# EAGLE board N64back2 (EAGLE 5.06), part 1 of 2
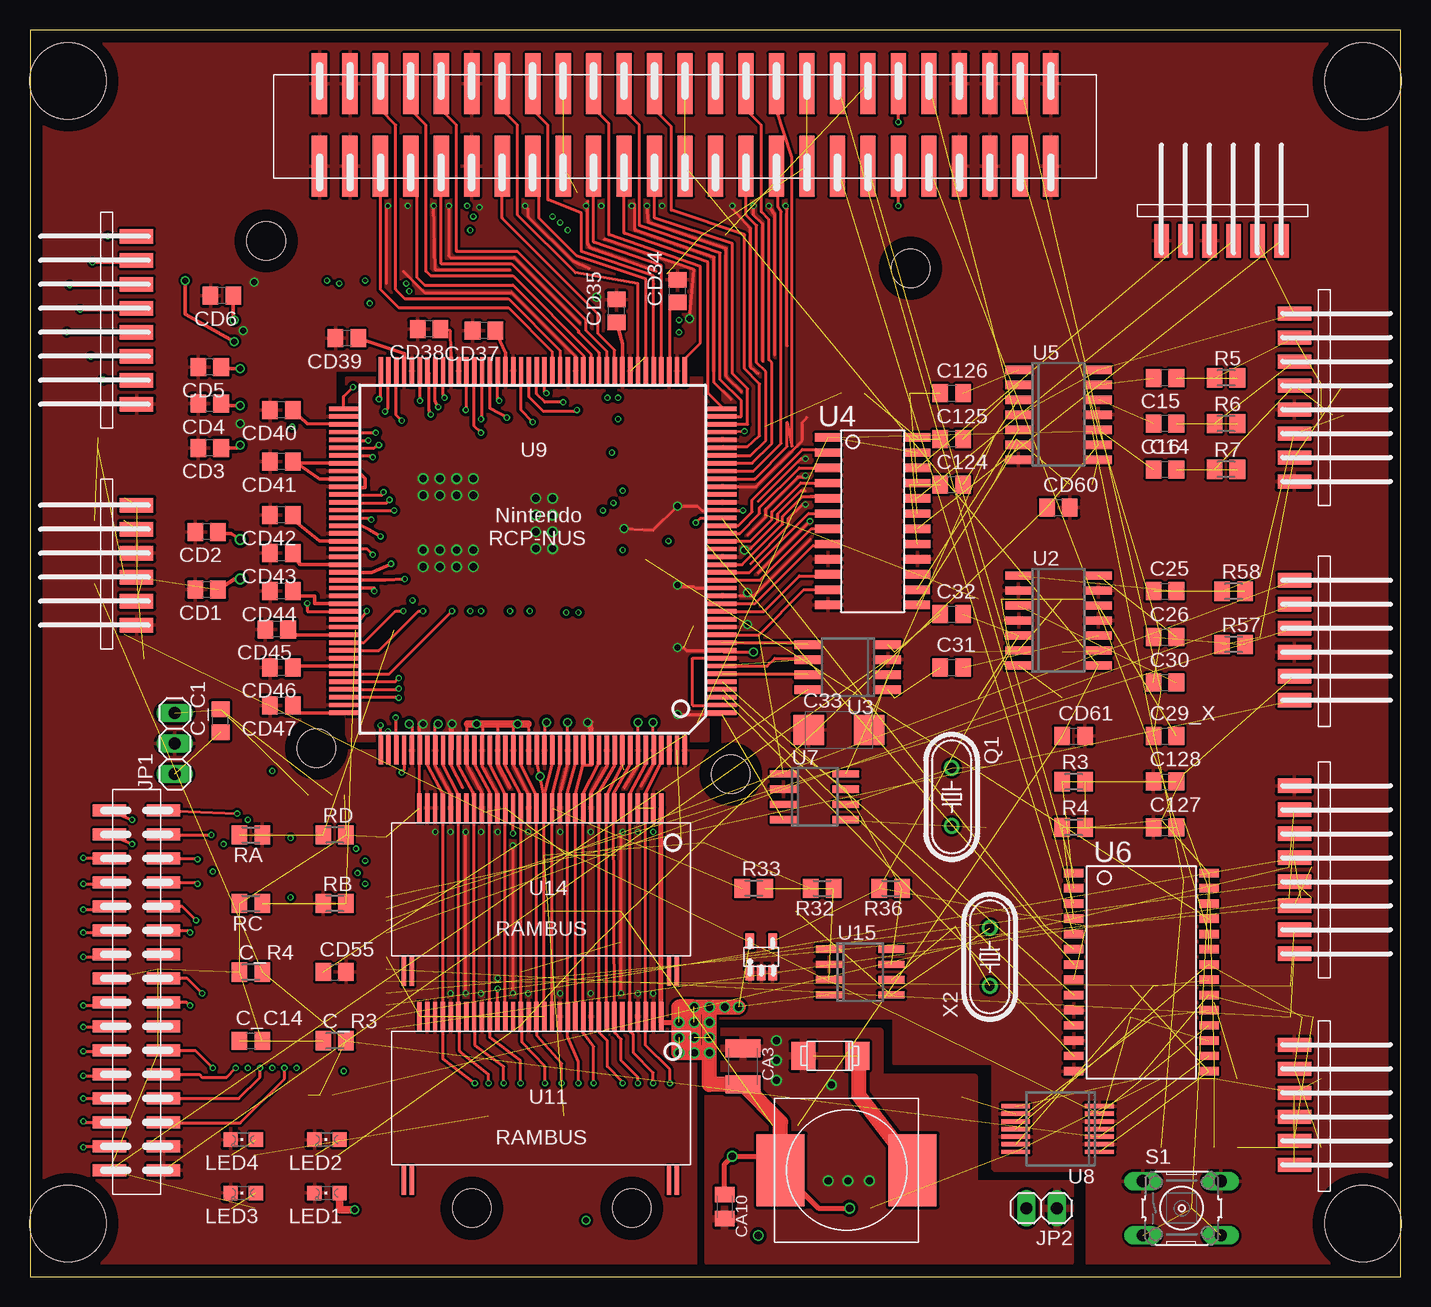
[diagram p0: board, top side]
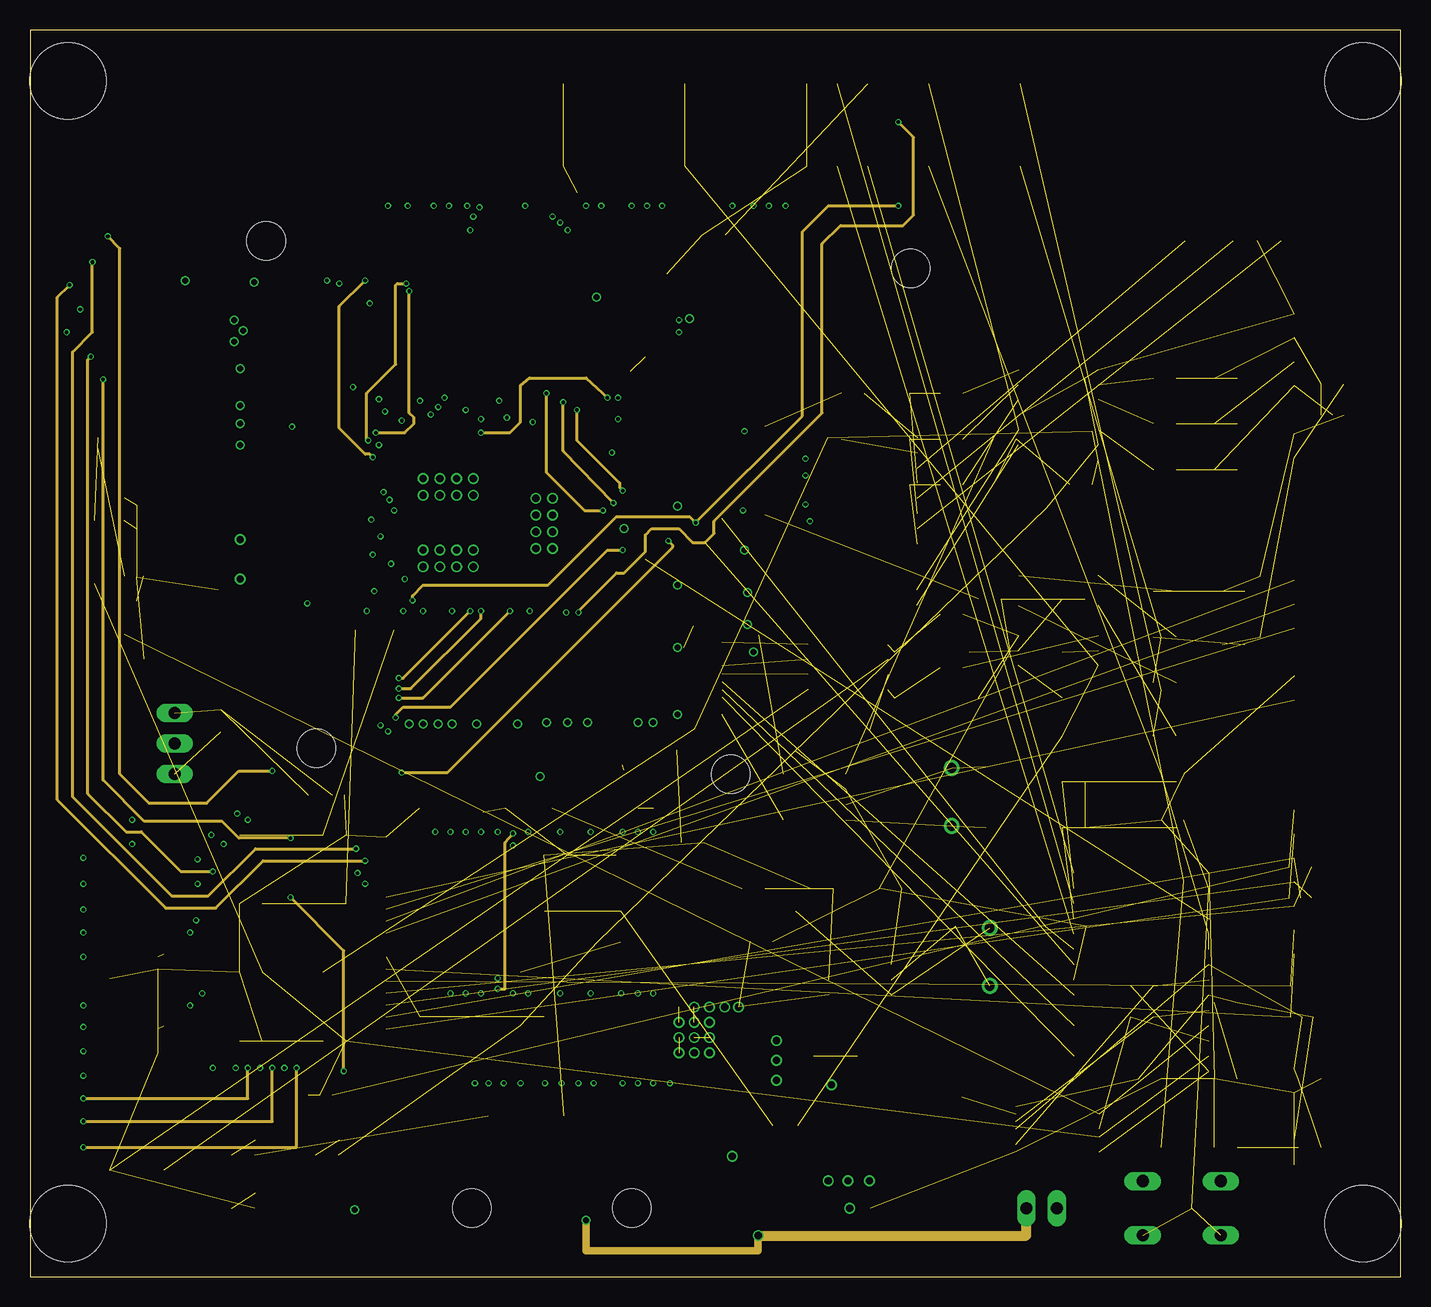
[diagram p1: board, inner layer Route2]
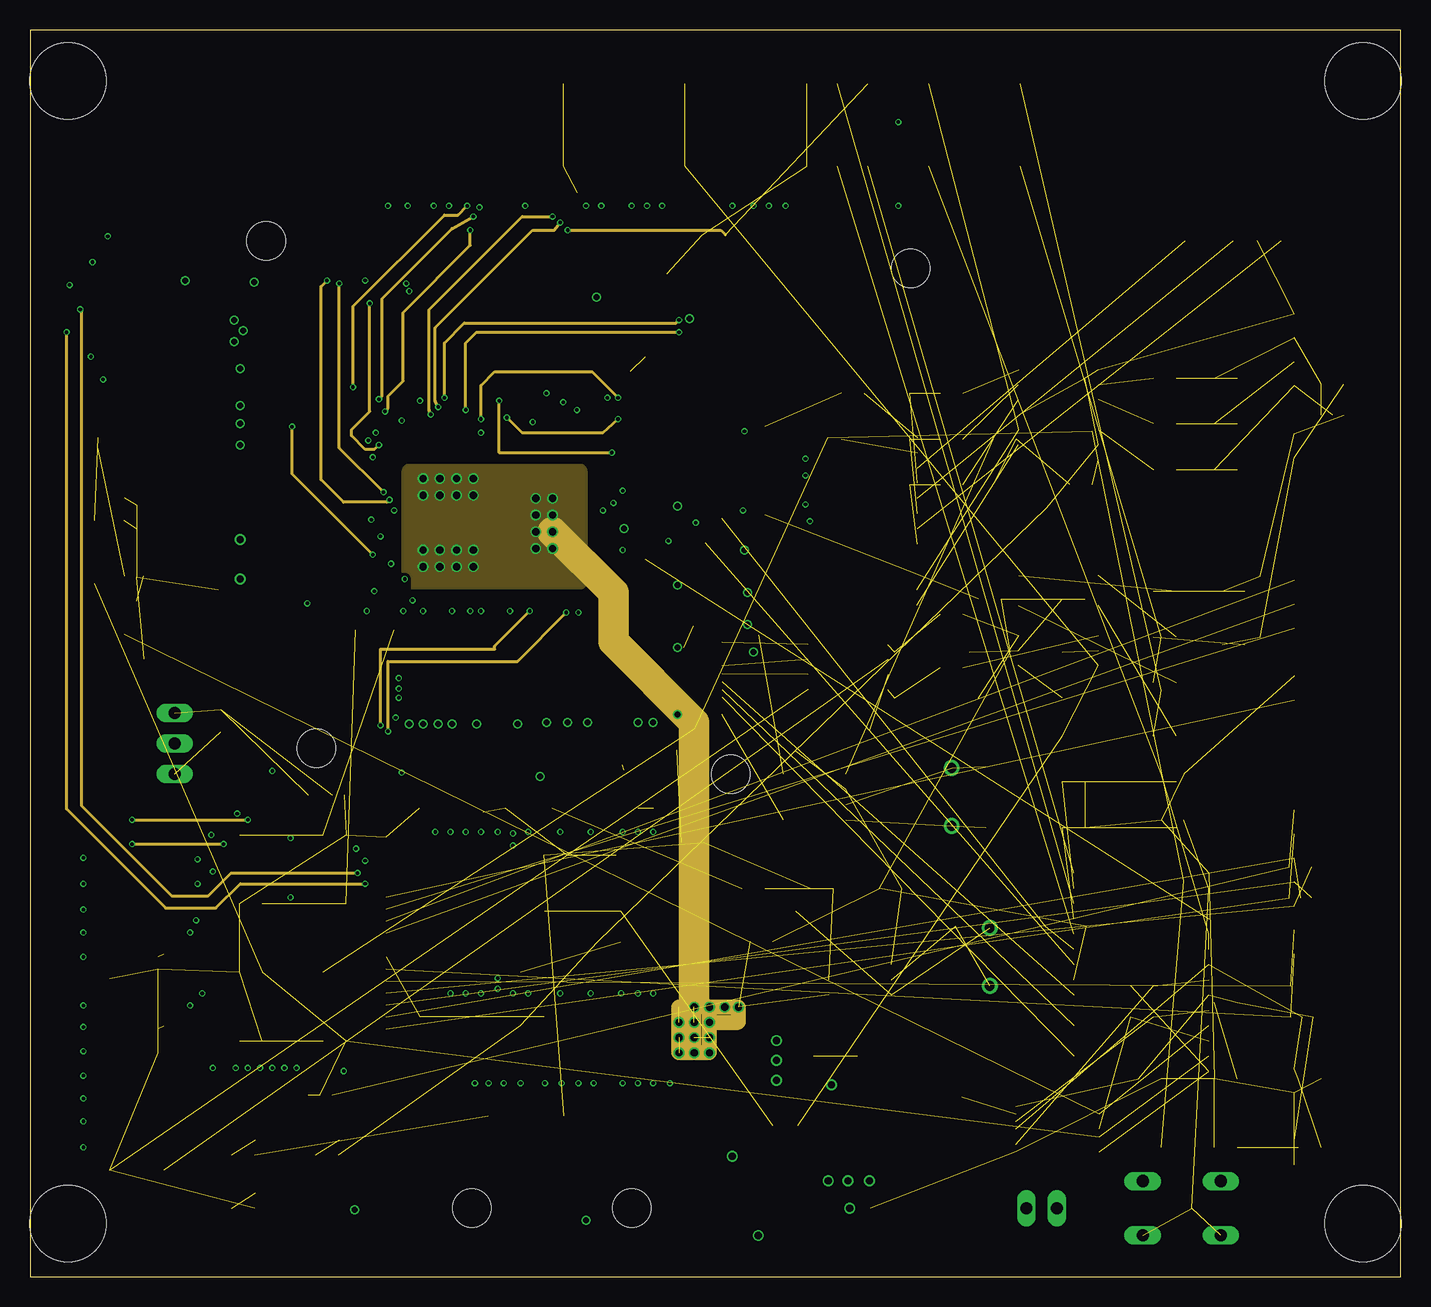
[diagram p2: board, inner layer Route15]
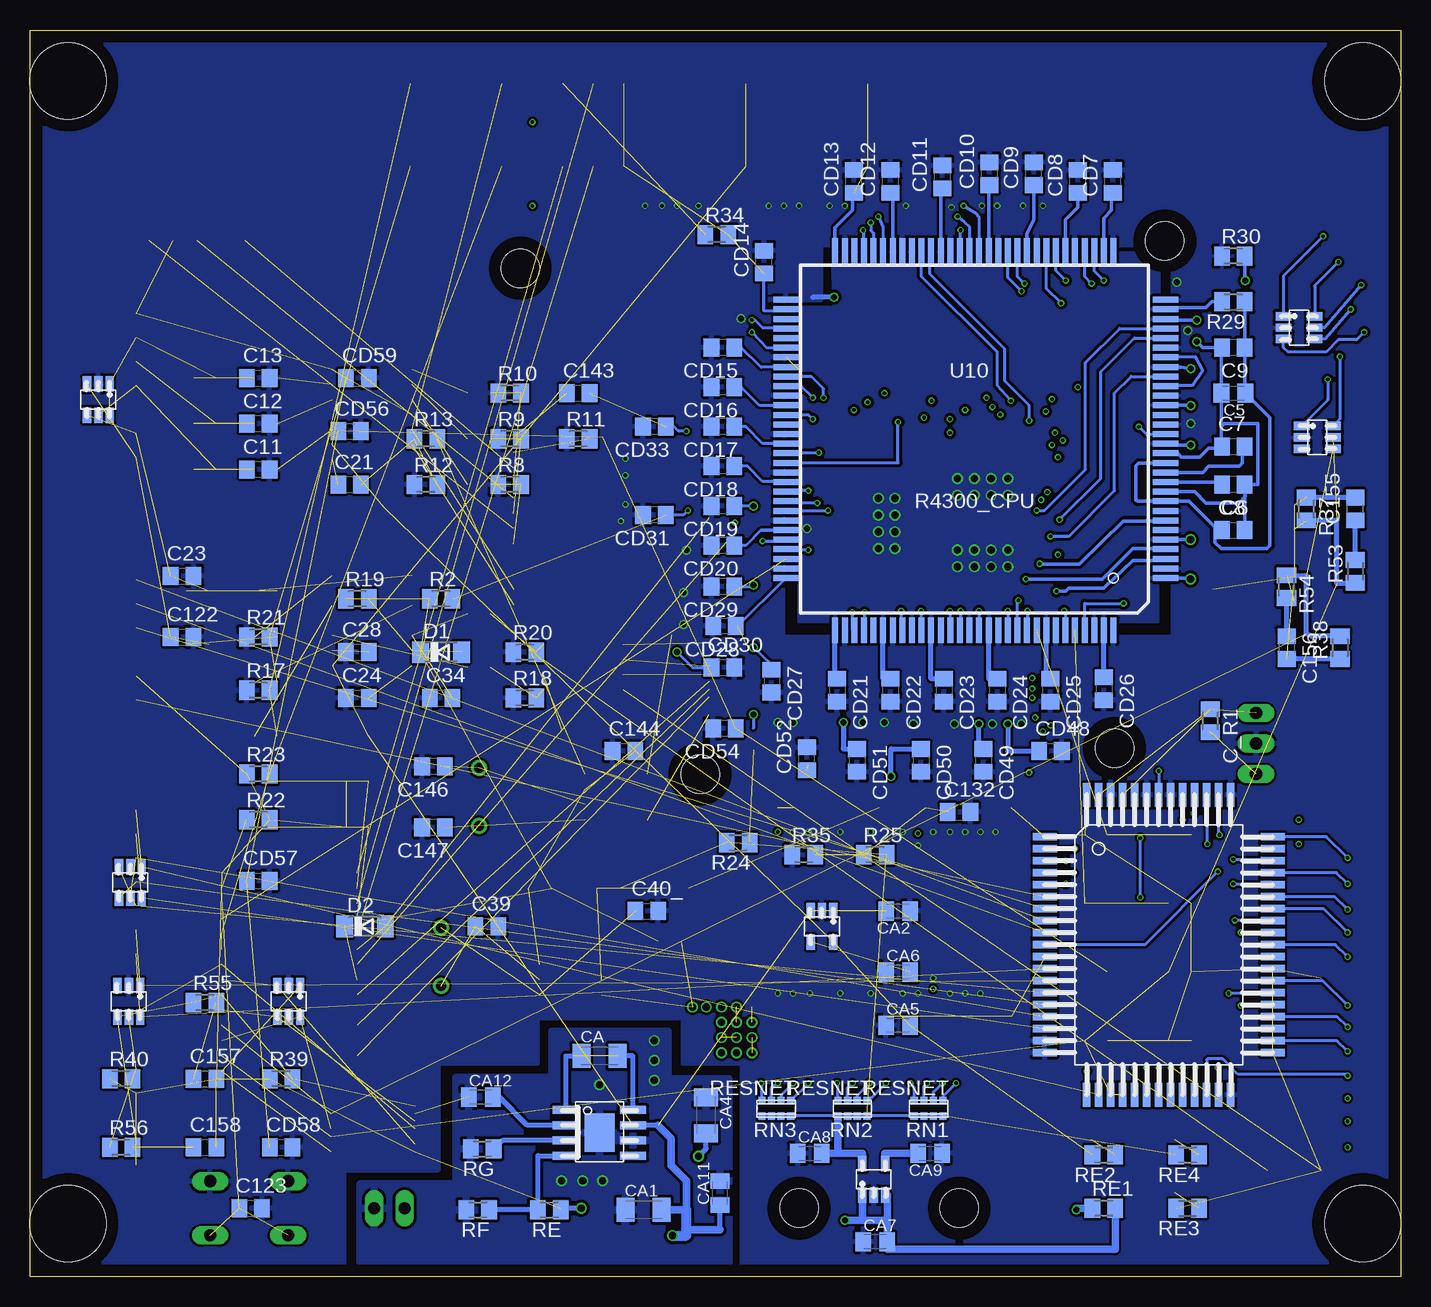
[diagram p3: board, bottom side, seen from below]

Size 114.28 x 103.94 mm. Coordinates in mm from the lower left corner, seen from the top.
Outline: 0,0 114.28,0 114.28,103.94 0,103.94 0,0
Copper layers (1*2+15*16): Top 0.035mm / dielectric 1.5mm / Route2 0.035mm / dielectric 0.15mm / Route15 0.035mm / dielectric 0.2mm / Bottom 0.035mm
Design rules "default *": minimum track width 5mil, minimum drill 10mil, track to track 6mil, track to pad 6mil, pad to pad 6mil, via to via 6mil, smd to smd 8mil, copper to edge 40mil, drill to drill 8mil, minimum pad ring 10mil, minimum via ring 4mil, stop-mask expansion 4mil, vias tented up to drill 0mil, thermal gap 10mil
Holes 3.2 mm at 19.68,86.36 23.88,44.07 58.42,41.91 36.83,5.71 50.16,5.71 73.41,84.07
Holes 6.35 mm at 3.17,99.69 111.12,99.69 3.17,4.45 111.12,4.45

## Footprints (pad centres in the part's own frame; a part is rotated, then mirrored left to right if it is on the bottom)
PSOP-8 = smd 0.65 x 2.2: 1 -1.84,-2.81; 2 -0.57,-2.81; 3 0.7,-2.81; 4 1.97,-2.81; 5 1.97,2.79; 6 0.7,2.79; 7 -0.57,2.79; 8 -1.84,2.79 | smd 3.2 x 2.5: 9 0.05,0
2MMPINHEAD-1X8 = smd 1.2 x 2.8: 1 -6,0; 2 -4,0; 3 -2,0; 4 0,0; 5 2,0; 6 4,0; 7 6,0; 8 8,0
C0805K = smd 1.3 x 1.6: 1 -1,0; 2 1,0
C0805 = smd 1.3 x 1.5: 1 -0.95,0; 2 0.95,0
C/6032-28R = smd 2.55 x 2.5: + 2.525,0; - -2.525,0
M0805 = smd 1.3 x 1.6: 1 -0.95,0; 2 0.95,0
PQFP64 = smd 0.65 x 2: 1 -9,-9.5; 2 -8,-9.5; 3 -7,-9.5; 4 -6,-9.5; 5 -5,-9.5; 6 -4,-9.5; 7 -3,-9.5; 8 -2,-9.5; 9 -1,-9.5; 10 0,-9.5; 11 1,-9.5; 12 2,-9.5; 13 3,-9.5; 14 4,-9.5; 15 5,-9.5; 16 6,-9.5; 17 7,-9.5; 18 8,-9.5; 19 9,-9.5; 33 9,9.5; 34 8,9.5; 35 7,9.5; 36 6,9.5; 37 5,9.5; 38 4,9.5; 39 3,9.5; 40 2,9.5; 41 1,9.5; 42 0,9.5; 43 -1,9.5; 44 -2,9.5; 45 -3,9.5; 46 -4,9.5; 47 -5,9.5; 48 -6,9.5; 49 -7,9.5; 50 -8,9.5; 51 -9,9.5 | smd 2 x 0.65: 20 12.5,-6; 21 12.5,-5; 22 12.5,-4; 23 12.5,-3; 24 12.5,-2; 25 12.5,-1; 26 12.5,0; 27 12.5,1; 28 12.5,2; 29 12.5,3; 30 12.5,4; 31 12.5,5; 32 12.5,6; 52 -12.5,6; 53 -12.5,5; 54 -12.5,4; 55 -12.5,3; 56 -12.5,2; 57 -12.5,1; 58 -12.5,0; 59 -12.5,-1; 60 -12.5,-2; 61 -12.5,-3; 62 -12.5,-4; 63 -12.5,-5; 64 -12.5,-6
C1206K = smd 1.5 x 2: 1 -1.5,0; 2 1.5,0
C1210K = smd 1.5 x 2.9: 1 -1.5,0; 2 1.5,0
2MMPINHEAD-1X6 = smd 1.2 x 2.8: 1 -4.73,-2.54; 2 -2.73,-2.54; 3 -0.73,-2.54; 4 1.27,-2.54; 5 3.27,-2.54; 6 5.27,-2.54
SOD80C = smd 1.4 x 1.8: A 1.7,0; C -1.7,0
STKYDIODE = smd 2.3 x 2: + 0,-2.2; - 0,2.3
1X03 = drill 1.016 long: 1 -2.54,0; 2 0,0; 3 2.54,0
1X02 = drill 1.016 long: 1 -1.27,0; 2 1.27,0
CHIPLED_0805 = smd 1.2 x 1.2: A 0,-1.05; C 0,1.05
HC49/S = drill 0.813 round: 1 -2.413,0; 2 2.413,0
RESARRAY = smd 0.6 x 0.6: 1 -1.2,-0.6; 2 -0.4,-0.6; 3 0.4,-0.6; 4 1.2,-0.6; 5 1.2,0.7; 6 0.4,0.7; 7 -0.4,0.7; 8 -1.2,0.7
B3F-10XX = drill 1.016 long: 1 -3.251,2.261; 2 3.251,2.261; 3 -3.251,-2.261; 4 3.251,-2.261
SC-74 = smd 0.7 x 1.3: 1 -0.95,-1.4; 2 0,-1.4; 3 0.95,-1.4; 4 0.95,1.2; 5 0,1.2; 6 -0.95,1.2
SO14 = smd 0.7 x 2.2: 1 -3.85,-3.295; 2 -2.6,-3.315; 3 -1.35,-3.31; 4 -0.1,-3.305; 5 1.15,-3.295; 6 2.4,-3.31; 7 3.65,-3.315; 8 3.65,3.345; 9 2.4,3.35; 10 1.15,3.35; 11 -0.1,3.35; 12 -1.35,3.35; 13 -2.6,3.35; 14 -3.85,3.35
SO8 = smd 0.7 x 2.2: 1 -1.85,-3.795; 2 -0.6,-3.815; 3 0.65,-3.81; 4 1.9,-3.805; 5 1.9,2.85; 6 0.65,2.85; 7 -0.6,2.85; 8 -1.85,2.85
SOT23-5 = smd 0.7 x 1.3: 1 -0.95,-1.3; 2 0,-1.3; 3 0.95,-1.3; 4 0.95,1.3; 5 -0.95,1.3
SO24 = smd 0.7 x 2.2: 1 -7.62,-3.707; 2 -6.35,-3.707; 3 -5.08,-3.707; 4 -3.81,-3.707; 5 -2.54,-3.707; 6 -1.27,-3.707; 7 0,-3.707; 8 1.27,-3.707; 9 2.54,-3.707; 10 3.81,-3.707; 11 5.08,-3.707; 12 6.35,-3.707; 13 6.35,3.707; 14 5.08,3.707; 15 3.81,3.739; 16 2.54,3.739; 17 1.27,3.739; 18 0,3.739; 19 -1.27,3.739; 20 -2.54,3.739; 21 -3.81,3.739; 22 -5.08,3.739; 23 -6.35,3.739; 24 -7.62,3.739
SO28W = smd 0.7 x 1.6: 1 -8.89,-5.707; 2 -7.62,-5.707; 3 -6.35,-5.707; 4 -5.08,-5.707; 5 -3.81,-5.707; 6 -2.54,-5.707; 7 -1.27,-5.707; 8 0,-5.707; 9 1.27,-5.707; 10 2.54,-5.707; 11 3.81,-5.707; 12 5.08,-5.707; 13 6.35,-5.707; 14 7.62,-5.707; 15 7.62,5.58; 16 6.35,5.58; 17 5.08,5.58; 18 3.81,5.58; 19 2.54,5.58; 20 1.27,5.58; 21 0,5.58; 22 -1.27,5.58; 23 -2.54,5.58; 24 -3.81,5.58; 25 -5.08,5.58; 26 -6.35,5.58; 27 -7.62,5.58; 28 -8.89,5.58
SO08 = smd 0.6 x 2.2: 1 -1.905,-2.6; 2 -0.635,-2.6; 3 0.635,-2.6; 4 1.905,-2.6; 5 1.905,2.6; 6 0.635,2.6; 7 -0.635,2.6; 8 -1.905,2.6
QSOP14 = smd 0.37 x 2.4: 1 -1.905,-3.56; 2 -1.27,-3.56; 3 -0.635,-3.56; 4 0,-3.56; 5 0.635,-3.56; 6 1.27,-3.56; 7 1.905,-3.56; 8 1.905,3.425; 9 1.27,3.425; 10 0.635,3.425; 11 0,3.425; 12 -0.635,3.425; 13 -1.27,3.425; 14 -1.905,3.425
PQFP160 = smd 2.4 x 0.37: 1 15.775,-12.675; 2 15.775,-12.025; 3 15.775,-11.375; 4 15.775,-10.725; 5 15.775,-10.075; 6 15.775,-9.425; 7 15.775,-8.775; 8 15.775,-8.125; 9 15.775,-7.475; 10 15.775,-6.825; 11 15.775,-6.175; 12 15.775,-5.525; 13 15.775,-4.875; 14 15.775,-4.225; 15 15.775,-3.575; 16 15.775,-2.925; 17 15.775,-2.275; 18 15.775,-1.625; 19 15.775,-0.975; 20 15.775,-0.325; 21 15.775,0.325; 22 15.775,0.975; 23 15.775,1.625; 24 15.775,2.275; 25 15.775,2.925; 26 15.775,3.575; 27 15.775,4.225; 28 15.775,4.875; 29 15.775,5.525; 30 15.775,6.175; 31 15.775,6.825; 32 15.775,7.475; 33 15.775,8.125; 34 15.775,8.775; 35 15.775,9.425; 36 15.775,10.075; 37 15.775,10.725; 38 15.775,11.375; 39 15.775,12.025; 40 15.775,12.675; 81 -15.775,12.675; 82 -15.775,12.025; 83 -15.775,11.375; 84 -15.775,10.725; 85 -15.775,10.075; 86 -15.775,9.425; 87 -15.775,8.775; 88 -15.775,8.125; 89 -15.775,7.475; 90 -15.775,6.825; 91 -15.775,6.175; 92 -15.775,5.525; 93 -15.775,4.875; 94 -15.775,4.225; 95 -15.775,3.575; 96 -15.775,2.925; 97 -15.775,2.275; 98 -15.775,1.625; 99 -15.775,0.975; 100 -15.775,0.325; 101 -15.775,-0.325; 102 -15.775,-0.975; 103 -15.775,-1.625; 104 -15.775,-2.275; 105 -15.775,-2.925; 106 -15.775,-3.575; 107 -15.775,-4.225; 108 -15.775,-4.875; 109 -15.775,-5.525; 110 -15.775,-6.175; 111 -15.775,-6.825; 112 -15.775,-7.475; 113 -15.775,-8.125; 114 -15.775,-8.775; 115 -15.775,-9.425; 116 -15.775,-10.075; 117 -15.775,-10.725; 118 -15.775,-11.375; 119 -15.775,-12.025; 120 -15.775,-12.675 | smd 0.37 x 2.4: 41 12.675,15.775; 42 12.025,15.775; 43 11.375,15.775; 44 10.725,15.775; 45 10.075,15.775; 46 9.425,15.775; 47 8.775,15.775; 48 8.125,15.775; 49 7.475,15.775; 50 6.825,15.775; 51 6.175,15.775; 52 5.525,15.775; 53 4.875,15.775; 54 4.225,15.775; 55 3.575,15.775; 56 2.925,15.775; 57 2.275,15.775; 58 1.625,15.775; 59 0.975,15.775; 60 0.325,15.775; 61 -0.325,15.775; 62 -0.975,15.775; 63 -1.625,15.775; 64 -2.275,15.775; 65 -2.925,15.775; 66 -3.575,15.775; 67 -4.225,15.775; 68 -4.875,15.775; 69 -5.525,15.775; 70 -6.175,15.775; 71 -6.825,15.775; 72 -7.475,15.775; 73 -8.125,15.775; 74 -8.775,15.775; 75 -9.425,15.775; 76 -10.075,15.775; 77 -10.725,15.775; 78 -11.375,15.775; 79 -12.025,15.775; 80 -12.675,15.775; 121 -12.675,-15.775; 122 -12.025,-15.775; 123 -11.375,-15.775; 124 -10.725,-15.775; 125 -10.075,-15.775; 126 -9.425,-15.775; 127 -8.775,-15.775; 128 -8.125,-15.775; 129 -7.475,-15.775; 130 -6.825,-15.775; 131 -6.175,-15.775; 132 -5.525,-15.775; 133 -4.875,-15.775; 134 -4.225,-15.775; 135 -3.575,-15.775; 136 -2.925,-15.775; 137 -2.275,-15.775; 138 -1.625,-15.775; 139 -0.975,-15.775; 140 -0.325,-15.775; 141 0.325,-15.775; 142 0.975,-15.775; 143 1.625,-15.775; 144 2.275,-15.775; 145 2.925,-15.775; 146 3.575,-15.775; 147 4.225,-15.775; 148 4.875,-15.775; 149 5.525,-15.775; 150 6.175,-15.775; 151 6.825,-15.775; 152 7.475,-15.775; 153 8.125,-15.775; 154 8.775,-15.775; 155 9.425,-15.775; 156 10.075,-15.775; 157 10.725,-15.775; 158 11.375,-15.775; 159 12.025,-15.775; 160 12.675,-15.775
QFP120 = smd 2.1 x 0.5: 1 15.95,-11.6; 2 15.95,-10.8; 3 15.95,-10; 4 15.95,-9.2; 5 15.95,-8.4; 6 15.95,-7.6; 7 15.95,-6.8; 8 15.95,-6; 9 15.95,-5.2; 10 15.95,-4.4; 11 15.95,-3.6; 12 15.95,-2.8; 13 15.95,-2; 14 15.95,-1.2; 15 15.95,-0.4; 16 15.95,0.4; 17 15.95,1.2; 18 15.95,2; 19 15.95,2.8; 20 15.95,3.6; 21 15.95,4.4; 22 15.95,5.2; 23 15.95,6; 24 15.95,6.8; 25 15.95,7.6; 26 15.95,8.4; 27 15.95,9.2; 28 15.95,10; 29 15.95,10.8; 30 15.95,11.6; 61 -15.7,11.6; 62 -15.7,10.8; 63 -15.7,10; 64 -15.7,9.2; 65 -15.7,8.4; 66 -15.7,7.6; 67 -15.7,6.8; 68 -15.7,6; 69 -15.7,5.2; 70 -15.7,4.4; 71 -15.7,3.6; 72 -15.7,2.8; 73 -15.7,2; 74 -15.7,1.2; 75 -15.7,0.4; 76 -15.7,-0.4; 77 -15.7,-1.2; 78 -15.7,-2; 79 -15.7,-2.8; 80 -15.7,-3.6; 81 -15.7,-4.4; 82 -15.7,-5.2; 83 -15.7,-6; 84 -15.7,-6.8; 85 -15.7,-7.6; 86 -15.7,-8.4; 87 -15.7,-9.2; 88 -15.7,-10; 89 -15.7,-10.8; 90 -15.7,-11.6 | smd 0.5 x 2.1: 31 11.6,15.7; 32 10.8,15.7; 33 10,15.7; 34 9.2,15.7; 35 8.4,15.7; 36 7.6,15.7; 37 6.8,15.7; 38 6,15.7; 39 5.2,15.7; 40 4.4,15.7; 41 3.6,15.7; 42 2.8,15.7; 43 2,15.7; 44 1.2,15.7; 45 0.4,15.7; 46 -0.4,15.7; 47 -1.2,15.7; 48 -2,15.7; 49 -2.8,15.7; 50 -3.6,15.7; 51 -4.4,15.7; 52 -5.2,15.7; 53 -6,15.7; 54 -6.8,15.7; 55 -7.6,15.7; 56 -8.4,15.7; 57 -9.2,15.7; 58 -10,15.7; 59 -10.8,15.7; 60 -11.6,15.7; 91 -11.6,-15.95; 92 -10.8,-15.95; 93 -10,-15.95; 94 -9.2,-15.95; 95 -8.4,-15.95; 96 -7.6,-15.95; 97 -6.8,-15.95; 98 -6,-15.95; 99 -5.2,-15.95; 100 -4.4,-15.95; 101 -3.6,-15.95; 102 -2.8,-15.95; 103 -2,-15.95; 104 -1.2,-15.95; 105 -0.4,-15.95; 106 0.4,-15.95; 107 1.2,-15.95; 108 2,-15.95; 109 2.8,-15.95; 110 3.6,-15.95; 111 4.4,-15.95; 112 5.2,-15.95; 113 6,-15.95; 114 6.8,-15.95; 115 7.6,-15.95; 116 8.4,-15.95; 117 9.2,-15.95; 118 10,-15.95; 119 10.8,-15.95; 120 11.6,-15.95
SHP32 = smd 0.37 x 2.4: 1 -10.075,-5.951; 2 -9.425,-5.951; 3 -8.775,-5.951; 4 -8.125,-5.951; 5 -7.475,-5.951; 6 -6.825,-5.951; 7 -6.175,-5.951; 8 -5.525,-5.951; 9 -4.875,-5.951; 10 -4.225,-5.951; 11 -3.575,-5.951; 12 -2.925,-5.951; 13 -2.275,-5.951; 14 -1.625,-5.951; 15 -0.975,-5.951; 16 -0.325,-5.951; 17 0.325,-5.951; 18 0.975,-5.951; 19 1.625,-5.951; 20 2.275,-5.951; 21 2.925,-5.951; 22 3.575,-5.951; 23 4.225,-5.951; 24 4.875,-5.951; 25 5.525,-5.951; 26 6.175,-5.951; 27 6.825,-5.951; 28 7.475,-5.951; 29 8.125,-5.951; 30 8.775,-5.951; 31 9.425,-5.951; 32 10.075,-5.951; M1 11.375,7.699; M2 10.725,7.699; M3 -10.725,7.699; M4 -11.375,7.699
PINHEAD-25X2 = smd 1.27 x 5.08: 1 -30.48,-3.302; 2 -30.48,3.556; 3 -27.94,-3.302; 4 -27.94,3.556; 5 -25.4,-3.302; 6 -25.4,3.556; 7 -22.86,-3.302; 8 -22.86,3.556; 9 -20.32,-3.302; 10 -20.32,3.556; 11 -17.78,-3.302; 12 -17.78,3.556; 13 -15.24,-3.302; 14 -15.24,3.556; 15 -12.7,-3.302; 16 -12.7,3.556; 17 -10.16,-3.302; 18 -10.16,3.556; 19 -7.62,-3.302; 20 -7.62,3.556; 21 -5.08,-3.302; 22 -5.08,3.556; 23 -2.54,-3.302; 24 -2.54,3.556; 25 0,-3.302; 26 0,3.556; 27 2.54,-3.302; 28 2.54,3.556; 29 5.08,-3.302; 30 5.08,3.556; 31 7.62,-3.302; 32 7.62,3.556; 33 10.16,-3.302; 34 10.16,3.556; 35 12.7,-3.302; 36 12.7,3.556; 37 15.24,-3.302; 38 15.24,3.556; 39 17.78,-3.302; 40 17.78,3.556; 41 20.32,-3.302; 42 20.32,3.556; 43 22.86,-3.302; 44 22.86,3.556; 45 25.4,-3.302; 46 25.4,3.556; 47 27.94,-3.302; 48 27.94,3.556; 49 30.48,-3.302; 50 30.48,3.556
2MMPINHEAD-16X2 = smd 1 x 2.8: 1 -16,-2.25; 2 -16,2.25; 3 -14,-2.25; 4 -14,2.25; 5 -12,-2.25; 6 -12,2.25; 7 -10,-2.25; 8 -10,2.25; 9 -8,-2.25; 10 -8,2.25; 11 -6,-2.25; 12 -6,2.25; 13 -4,-2.25; 14 -4,2.25; 15 -2,-2.25; 16 -2,2.25; 17 0,-2.25; 18 0,2.25; 19 2,-2.25; 20 2,2.25; 21 4,-2.25; 22 4,2.25; 23 6,-2.25; 24 6,2.25; 25 8,-2.25; 26 8,2.25; 27 10,-2.25; 28 10,2.25; 29 12,-2.25; 30 12,2.25; 31 14,-2.25; 32 14,2.25
INDUCTOR = smd 6 x 4: 1 0,5.5; 2 0,-5.5

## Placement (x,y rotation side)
3V3  LM22680  [PSOP-8]  66.8,12.06 270 bottom
AV  PINHEAD-1X8  [2MMPINHEAD-1X8]  105.41,74.3 270 top
BUTT1  PINHEAD-1X8  [2MMPINHEAD-1X8]  8.89,78.74 90 top
BUTT2  PINHEAD-1X8  [2MMPINHEAD-1X8]  105.41,34.93 270 top
C5  [C0805K]  13.97,73.66 180 bottom
C6  [C0805]  13.97,66.04 180 bottom
C7  [C0805]  13.97,69.21 0 bottom
C8  [C0805]  13.97,62.23 0 bottom
C9  [C0805]  13.97,77.47 180 bottom
C11  [C0805]  95.25,67.31 0 bottom
C12  [C0805]  95.25,71.12 0 bottom
C13  [C0805]  95.25,74.93 0 bottom
C14  [C0805]  94.62,67.31 0 top
C15  10uF  [C0805]  94.62,74.93 180 top
C16  10uF  [C0805]  94.62,71.12 180 top
C21  [C0805]  87.63,66.04 0 bottom
C23  [C0805]  101.6,58.42 0 bottom
C24  10uF  [C0805]  87,48.26 0 bottom
C25  10uF  [C0805]  94.62,57.15 0 top
C26  10uF  [C0805]  94.62,53.34 0 top
C28  10uF  [C0805]  87,52.07 0 bottom
C29_X  [C0805]  94.62,45.09 0 top
C30  [C0805]  94.62,49.53 0 top
C31  [C0805]  76.84,50.8 0 top
C32  [C0805]  76.84,55.25 0 top
C33  68uF  [C/6032-28R]  67.44,45.59 0 top
C34  10uF  [C0805]  80.01,48.26 0 bottom
C39  [C0805]  76.2,29.21 0 bottom
C40_  [C0805]  62.87,30.48 0 bottom
C122  [C0805]  101.6,53.34 0 bottom
C123  [C0805]  95.89,5.71 0 bottom
C124  c  [C0805]  76.84,66.04 0 top
C125  c  [C0805]  76.84,69.85 0 top
C126  c  [C0805]  76.84,73.66 0 top
C127  [C0805]  94.62,37.47 0 top
C128  10uF  [C0805]  94.62,41.28 0 top
C132  [C0805]  36.83,38.74 0 bottom
C143  c  [C0805]  68.58,73.66 0 bottom
C144  [C0805]  64.77,43.82 0 bottom
C146  [C0805]  80.65,42.55 180 bottom
C147  [C0805]  80.65,37.47 180 bottom
C155  [C0805]  3.81,64.01 90 bottom
C156  [C0805]  9.52,52.45 270 bottom
C157  [C0805]  99.69,16.51 0 bottom
C158  [C0805]  99.69,10.79 0 bottom
C_C1  [C0805]  15.88,46.36 90 top
C_C14  [C0805]  18.41,19.68 0 top
C_R1  1M0  [M0805]  15.88,46.36 270 bottom
C_R3  130R  [M0805]  25.4,19.68 0 top
C_R4  150K  [M0805]  18.41,25.4 0 top
C_U1  CNT-NUS  [PQFP64]  20.19,27.69 270 bottom
CA  [C1206K]  66.8,18.41 0 bottom
CA1  [C1206K]  63.12,5.59 0 bottom
CA2  [C0805K]  41.91,30.48 180 bottom
CA3  [C1210K]  59.44,17.53 270 top
CA4  [C1206K]  57.91,13.46 270 bottom
CA5  [C0805K]  41.91,20.95 0 bottom
CA6  470pF  [C0805K]  41.91,25.4 0 bottom
CA7  [C0805K]  43.82,2.92 0 bottom
CA8  [C0805K]  49.28,10.29 0 bottom
CA9  470pF  [C0805K]  39.24,10.29 180 bottom
CA10  [C0805K]  57.91,5.84 270 top
CA11  [C0805K]  56.77,6.98 90 bottom
CA12  [C0805K]  76.71,14.99 0 bottom
CD1  10uF  [C0805]  14.73,57.28 180 top
CD2  10uF  [C0805]  14.73,62.1 180 top
CD3  10uF  [C0805]  14.99,69.09 180 top
CD4  10uF  [C0805]  14.99,72.77 180 top
CD5  10uF  [C0805]  14.99,75.82 180 top
CD6  10uF  [C0805]  16,81.79 180 top
CD7  10uF  [C0805]  24,91.31 90 bottom
CD8  10uF  [C0805]  26.92,91.31 90 bottom
CD9  10uF  [C0805]  30.61,91.95 90 bottom
CD10  10uF  [C0805]  34.29,91.95 90 bottom
CD11  10uF  [C0805]  38.23,91.69 90 bottom
CD12  10uF  [C0805]  42.54,91.31 90 bottom
CD13  10uF  [C0805]  45.59,91.31 90 bottom
CD14  10uF  [C0805]  53.09,84.58 90 bottom
CD15  10uF  [C0805]  56.51,77.47 180 bottom
CD16  10uF  [C0805]  56.51,74.17 180 bottom
CD17  10uF  [C0805]  56.51,70.87 180 bottom
CD18  10uF  [C0805]  56.51,67.56 180 bottom
CD19  10uF  [C0805]  56.51,64.26 180 bottom
CD20  10uF  [C0805]  56.51,60.96 180 bottom
CD21  10uF  [C0805]  46.99,48.9 270 bottom
CD22  10uF  [C0805]  42.54,48.9 270 bottom
CD23  10uF  [C0805]  38.1,48.9 270 bottom
CD24  10uF  [C0805]  33.65,48.9 270 bottom
CD25  10uF  [C0805]  29.21,48.9 270 bottom
CD26  10uF  [C0805]  24.77,49.02 270 bottom
CD27  10uF  [C0805]  52.45,49.66 270 bottom
CD28  10uF  [C0805]  56.39,54.23 180 bottom
CD29  10uF  [C0805]  56.51,57.53 180 bottom
CD30  10uF  [C0805]  56.51,50.8 0 bottom
CD31  10uF  [C0805]  62.23,63.5 180 bottom
CD33  10uF  [C0805]  62.23,70.87 180 bottom
CD34  10uF  [C0805]  53.98,82.17 90 top
CD35  10uF  [C0805]  48.9,80.52 90 top
CD37  10uF  [C0805]  37.85,78.87 180 top
CD38  10uF  [C0805]  33.27,78.99 180 top
CD39  10uF  [C0805]  26.42,78.23 180 top
CD40  10uF  [C0805]  20.95,72.26 180 top
CD41  10uF  [C0805]  20.95,67.94 180 top
CD42  10uF  [C0805]  20.95,63.5 180 top
CD43  10uF  [C0805]  20.95,60.33 180 top
CD44  10uF  [C0805]  20.95,57.15 180 top
CD45  10uF  [C0805]  20.57,53.98 180 top
CD46  10uF  [C0805]  20.95,50.8 180 top
CD47  10uF  [C0805]  20.95,47.62 180 top
CD48  10uF  [C0805]  29.21,43.82 0 bottom
CD49  10uF  [C0805]  34.8,43.05 270 bottom
CD50  10uF  [C0805]  40.01,43.05 270 bottom
CD51  10uF  [C0805]  45.34,43.05 270 bottom
CD52  10uF  [C0805]  49.53,43.18 90 bottom
CD54  10uF  [C0805]  56.39,45.72 180 bottom
CD55  10uF  [C0805]  25.4,25.4 0 top
CD56  10uF  [C0805]  87.63,70.48 0 bottom
CD57  10uF  [C0805]  95.25,33.02 0 bottom
CD58  10uF  [C0805]  93.34,10.79 0 bottom
CD59  10uF  [C0805]  87,74.93 0 bottom
CD60  10uF  [C0805]  85.72,64.14 0 top
CD61  10uF  [C0805]  87,45.09 0 top
CONT1  PINHEAD-1X6  [2MMPINHEAD-1X6]  6.35,59.05 90 top
CONT2  PINHEAD-1X6  [2MMPINHEAD-1X6]  107.95,14.61 270 top
D1  PMLL4150  [SOD80C]  80.01,52.07 0 bottom
D2  PMLL4150  [SOD80C]  86.36,29.21 0 bottom
DA  STKYDIODE  [STKYDIODE]  66.68,18.41 270 top
JOY  PINHEAD-1X6  [2MMPINHEAD-1X6]  107.95,53.34 270 top
JP1  [1X03]  12.06,44.45 90 top
JP2  [1X02]  84.33,5.71 180 top
LED1  [CHIPLED_0805]  24.77,6.98 90 top
LED2  [CHIPLED_0805]  24.77,11.43 90 top
LED3  [CHIPLED_0805]  17.78,6.98 90 top
LED4  [CHIPLED_0805]  17.78,11.43 90 top
Q1  [HC49/S]  76.84,40.01 270 top
R2  2k0  [M0805]  80.01,56.52 0 bottom
R3  30K  [M0805]  87,41.28 0 top
R4  68K  [M0805]  87,37.47 0 top
R5  75R  [M0805]  99.69,74.93 0 top
R6  75R  [M0805]  99.69,71.12 0 top
R7  75R  [M0805]  99.69,67.31 0 top
R8  110R  [M0805]  74.29,66.04 0 bottom
R9  110R  [M0805]  74.29,69.85 0 bottom
R10  110R  [M0805]  74.29,73.66 0 bottom
R11  10k  [M0805]  68.58,69.85 0 bottom
R12  820R  [M0805]  81.28,66.04 0 bottom
R13  4k3  [M0805]  81.28,69.85 0 bottom
R17  1K  [M0805]  95.25,48.9 0 bottom
R18  10k  [M0805]  73.03,48.26 0 bottom
R19  180k  [M0805]  87,56.52 0 bottom
R20  10k  [M0805]  73.03,52.07 0 bottom
R21  1k  [M0805]  95.25,53.34 0 bottom
R22  47K  [M0805]  95.25,38.1 0 bottom
R23  10k  [M0805]  95.25,41.91 0 bottom
R24  24R  [M0805]  55.24,36.2 180 bottom
R25  130R  [M0805]  43.82,35.18 0 bottom
R29  4R7  [M0805]  13.97,81.28 180 bottom
R30  4R7  [M0805]  13.97,85.09 0 bottom
R32  150R  [M0805]  66.04,32.38 180 top
R33  33R  [M0805]  60.32,32.38 0 top
R34  47K  [M0805]  57.02,86.87 0 bottom
R35  390R  [M0805]  49.78,35.18 0 bottom
R36  51K  [M0805]  71.75,32.38 180 top
R37  750R  [M0805]  7.87,64.01 270 bottom
R38  750R  [M0805]  5.08,52.45 90 bottom
R39  750R  [M0805]  93.34,16.51 0 bottom
R40  750R  [M0805]  106.68,16.51 0 bottom
R53  130R  [M0805]  3.81,58.8 90 bottom
R54  130R  [M0805]  9.52,57.53 270 bottom
R55  130R  [M0805]  99.69,22.86 0 bottom
R56  130R  [M0805]  106.68,10.79 0 bottom
R57  1k  [M0805]  100.33,52.71 0 top
R58  1k  [M0805]  100.33,57.15 0 top
RA  OPEN  [M0805]  18.41,36.83 180 top
RB  0R  [M0805]  25.4,31.11 0 top
RC  33K  [M0805]  18.41,31.11 180 top
RD  33K  [M0805]  25.4,36.83 0 top
RE  1K4  [M0805]  70.99,5.59 180 bottom
RE1  1K4  [M0805]  24.77,5.71 0 bottom
RE2  1K4  [M0805]  24.77,10.16 180 bottom
RE3  1K4  [M0805]  17.78,5.71 180 bottom
RE4  1K4  [M0805]  17.78,10.16 180 bottom
RF  1K0  [M0805]  76.96,5.59 180 bottom
RG  191k  [M0805]  76.58,10.67 180 bottom
RGB  PINHEAD-1X6  [2MMPINHEAD-1X6]  99.06,88.9 0 top
RN1  RESNET  [RESARRAY]  39.37,14.1 180 bottom
RN2  RESNET  [RESARRAY]  45.72,14.1 180 bottom
RN3  RESNET  [RESARRAY]  52.07,14.1 180 bottom
S1  [B3F-10XX]  96.01,5.71 0 top
TVS1  TVS  [SC-74]  108.59,73.02 180 bottom
TVS2  TVS  [SC-74]  92.71,22.86 180 bottom
TVS3  TVS  [SC-74]  6.86,69.98 270 bottom
TVS4  TVS  [SC-74]  106.05,22.86 180 bottom
TVS5  TVS  [SC-74]  8.38,79.12 270 bottom
TVS6  TVS  [SC-74]  105.92,32.77 180 bottom
U2  AMP-NUS  [SO14]  85.72,54.61 270 top
U3  9480  [SO8]  67.69,50.8 90 top
U3_  U3  [SOT23-5]  60.96,26.67 0 top
U4  VDCNUS  [SO24]  70.23,62.36 270 top
U5  ENC-NUS  [SO14]  85.72,71.75 270 top
U6  PIF  [SO28W]  92.71,24.77 270 top
U7  MX8330MC  [SO08]  65.41,40.01 270 top
U8  74LS125J  [QSOP14]  85.6,12.32 90 top
U9  N64_RCP  [PQFP160]  41.91,59.69 0 top
U10  R4300_CPU  [QFP120]  35.56,69.85 0 bottom
U11  RDRAM18_NUS  [SHP32]  42.54,15.75 180 top
U12  MIC5219  [SOT23-5]  43.94,8.13 0 bottom
U13  MIC5219  [SOT23-5]  48.26,29.21 180 bottom
U14  RDRAM18_NUS  [SHP32]  42.54,33.15 180 top
U15  MX8330MC  [SO08]  69.22,25.4 270 top
U$37  PINHEAD-25X2  [PINHEAD-25X2]  54.61,95.88 0 top
U$38  PINHEAD-16X2SMALLER  [2MMPINHEAD-16X2]  8.89,22.86 270 top
U$52  INDUCTOR  [INDUCTOR]  68.07,8.89 270 top
X2  [HC49/S]  80.01,26.67 90 top

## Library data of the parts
3V3 AV BUTT1 BUTT2 C_U1 CONT1 CONT2 DA JOY RGB RN1-RN3 TVS1-TVS6 U2 U3 U3_ U4-U15 U$37 U$38 U$52 = Nintendo-64
C5-C9 C11-C16 C21 C23-C26 C28 C29_X C30-C34 C39 C40_ C122-C128 C132 C143 C144 C146 C147 C155-C158 C_C1 C_C14 C_R1 C_R3 C_R4 CA CA1-CA12 CD1-CD31 CD33-CD35 CD37-CD52 CD54-CD61 R2-R13 R17-R25 R29 R30 R32-R40 R53-R58 RA RB RC RD RE RE1-RE4 RF RG = rcl
D1 D2 = diode
JP1 JP2 = pinhead
LED1-LED4 = led
Q1 X2 = crystal
S1 = switch-omron

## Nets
3V3: C143.2 C155.2 C156.2 C157.2 C158.2 C_C14.2 C_R4.1 C_U1.1 C_U1.11 C_U1.33 C_U1.40 C_U1.64 CA3.2 CA4.2 CA10.1 CD1.1 CD2.1 CD3.1 CD4.1 CD5.1 CD6.1 CD7.1 CD8.1 CD9.1 CD10.1 CD11.1 CD12.1 CD13.1 CD14.1 CD15.1 CD16.1 CD17.1 CD18.1 CD19.1 CD20.1 CD21.1 CD22.1 CD23.1 CD24.1 CD25.1 CD26.1 CD27.1 CD28.1 CD29.1 CD30.1 CD31.1 CD33.1 CD34.1 CD35.1 CD37.1 CD38.1 CD39.1 CD40.1 CD41.1 CD42.1 CD43.1 CD44.1 CD45.1 CD46.1 CD47.1 CD48.1 CD49.1 CD50.1 CD51.1 CD52.1 CONT1.3 CONT1.6 CONT2.3 CONT2.6 JOY.5 R2.2 R3.2 R4.2 R22.2 R23.1 R29.2 R34.2 R37.1 R38.1 R39.1 R40.1 RC.2 RD.2 RE3.2 RE.1 U3.8 U3_.5 U4.15 U6.28 U7.4 U8.14 U9.1 U9.9 U9.13 U9.17 U9.22 U9.27 U9.29 U9.37 U9.43 U9.49 U9.56 U9.64 U9.71 U9.77 U9.83 U9.88 U9.90 U9.98 U9.101 U9.106 U9.110 U9.114 U9.120 U9.126 U9.130 U9.141 U9.143 U9.147 U9.148 U9.152 U10.1 U10.5 U10.15 U10.19 U10.23 U10.28 U10.29 U10.32 U10.36 U10.40 U10.44 U10.49 U10.52 U10.54 U10.58 U10.60 U10.62 U10.63 U10.68 U10.72 U10.76 U10.80 U10.85 U10.90 U10.91 U10.96 U10.99 U10.101 U10.105 U10.107 U10.113 U10.118 U10.119 U11.1 U11.8 U11.12 U11.16 U11.20 U11.32 U14.1 U14.8 U14.12 U14.16 U14.32 U15.4 U$37.17 U$37.18 U$37.33 U$37.34 U$38.15 U$38.31 U$52.2
+3V3: CD54.1 CD55.1 CD56.1 CD57.1 CD58.1 U4.1
+5V: AV.1 CA5.2 CD59.1 CD60.1 RE2.2 RGB.5 U5.4 U5.9 U5.14 U13.5
+12V: 3V3.7 CA1.2 CA2.2 CA7.2 CA11.1 CD61.1 JP2.2 RE1.2 U2.8 U12.1 U12.3 U13.1 U13.3 U$37.25 U$37.26
/COLDRESET: D2.A U6.6 U9.26 U10.110 U$37.39
/INT2: U6.25 U10.88
ADJ: 3V3.4 RE.2 RF.1
C16X: C16.1 R6.2
C_C11: C_C1.1 C_R1.2 JP1.1
DQ0: RN1.1 U9.127 U11.29 U14.29
DQ1: RN1.2 U9.129 U11.27 U14.27
DQ2: RN1.3 U9.131 U11.25 U14.25
DQ3: RN1.4 U9.133 U11.23 U14.23
DQ4: RN2.2 U9.139 U11.17 U14.17
DQ5: RN2.4 U9.149 U11.11 U14.11
DQ6: RN3.1 U9.151 U11.9 U14.9
DQ7: RN3.3 U9.155 U11.5 U14.5
DQ8: RN3.4 U9.157 U11.3 U14.3
FROM_U15: D1.C D2.C R2.1 R19.1 R36.2 U3_.4 U6.8
FSEL: C144.2 R36.1 U7.7 U15.7
FSO1: R32.1 R33.2 U15.3
GND: 3V3.6 3V3.9 AV.5 AV.8 BUTT1.1 BUTT2.1 C11.2 C12.2 C13.2 C23.2 C24.1 C28.1 C33.- C34.1 C39.2 C40_.2 C122.2 C123.2 C127.1 C128.1 C132.2 C144.1 C146.2 C147.2 C_U1.18 C_U1.19 C_U1.32 C_U1.52 C_U1.57 C_U1.59 C_U1.62 CA1.1 CA2.1 CA3.1 CA4.1 CA5.1 CA6.1 CA7.1 CA8.1 CA9.1 CA10.2 CA11.2 CA12.1 CD1.2 CD2.2 CD3.2 CD4.2 CD5.2 CD6.2 CD7.2 CD8.2 CD9.2 CD10.2 CD11.2 CD12.2 CD13.2 CD14.2 CD15.2 CD16.2 CD17.2 CD18.2 CD19.2 CD20.2 CD21.2 CD22.2 CD23.2 CD24.2 CD25.2 CD26.2 CD27.2 CD28.2 CD29.2 CD30.2 CD31.2 CD33.2 CD34.2 CD35.2 CD37.2 CD38.2 CD39.2 CD40.2 CD41.2 CD42.2 CD43.2 CD44.2 CD45.2 CD46.2 CD47.2 CD48.2 CD49.2 CD50.2 CD51.2 CD52.2 CD54.2 CD55.2 CD56.2 CD57.2 CD58.2 CD59.2 CD60.2 CD61.2 CONT1.1 CONT1.4 CONT2.1 CONT2.4 DA.+ JOY.4 JP1.2 JP2.1 LED1.C LED2.C LED3.C LED4.C R8.1 R9.1 R10.1 R11.1 R12.1 R17.1 R18.1 R20.1 R21.1 R30.1 R35.1 RA.1 RB.1 RF.2 RG.2 RGB.1 RGB.3 S1.1 S1.2 TVS1.2 TVS2.2 TVS3.2 TVS4.2 TVS5.2 U2.2 U2.4 U2.11 U2.13 U3.3 U3_.1 U3_.2 U3_.3 U4.9 U4.12 U4.16 U5.7 U5.11 U6.10 U6.12 U6.14 U7.2 U8.2 U8.5 U8.7 U8.9 U8.12 U9.2 U9.8 U9.12 U9.16 U9.21 U9.28 U9.30 U9.36 U9.42 U9.48 U9.55 U9.63 U9.70 U9.76 U9.82 U9.89 U9.91 U9.97 U9.100 U9.105 U9.109 U9.113 U9.119 U9.125 U9.128 U9.132 U9.134 U9.136 U9.138 U9.140 U9.142 U9.145 U9.150 U9.154 U9.156 U9.158 U9.160 U10.2 U10.6 U10.8 U10.17 U10.20 U10.25 U10.30 U10.31 U10.35 U10.39 U10.43 U10.48 U10.53 U10.59 U10.61 U10.67 U10.71 U10.75 U10.79 U10.84 U10.89 U10.92 U10.97 U10.102 U10.108 U10.114 U10.120 U11.2 U11.4 U11.10 U11.14 U11.18 U11.24 U11.28 U11.30 U11.31 U12.2 U13.2 U14.2 U14.4 U14.10 U14.14 U14.18 U14.22 U14.24 U14.28 U14.30 U14.31 U15.2 U$37.1 U$37.2 U$37.3 U$37.4 U$37.11 U$37.12 U$37.43 U$37.44 U$37.45 U$37.46 U$37.49 U$37.50 U$38.30 U$38.32
INT0: U9.80 U10.46
LEFT_AUDIO: C30.1 R21.2 U$37.47
N$1: C156.1 R54.2
N$2: C155.1 R53.2
N$3: U4.11 U7.1 U9.11
N$4: R24.1 U9.159
N$5: C147.1 Q1.2 U7.5
N$6: C146.1 Q1.1 U7.6
N$7: BUTT1.2 C_U1.20 TVS3.1
N$8: RGB.2 U4.22
N$9: RGB.4 U4.20
N$10: U6.9 U9.5
N$11: U6.11 U9.4
N$12: U6.13 U9.3
N$13: TVS2.1 U6.15 U8.1
N$14: C_R3.2 C_R4.2 C_U1.22 C_U1.23 CONT1.5 R37.2 R53.1 TVS3.5 U6.16 U8.3
N$15: BUTT1.3 C_U1.10 TVS3.6
N$16: LED1.A RE1.1
N$17: CONT1.2 R38.2 R54.1 TVS3.4 U6.18 U8.6
N$18: TVS2.4 U6.19 U8.10
N$19: CONT2.5 R39.2 R55.1 TVS4.4 U6.20 U8.8
N$20: TVS2.3 U6.21 U8.13
N$21: CONT2.2 R40.2 R56.1 TVS4.5 U6.22 U8.11
N$22: U4.2 U9.25
N$23: U9.116 U10.104
N$24: TVS2.6 U6.17 U8.4
N$25: U9.62 U10.78
N$26: U9.60 U10.82
N$27: C123.1 R22.1 S1.3 S1.4 U6.27
N$28: U4.3 U9.24
N$29: RB.2 RC.1 U10.116
N$31: U9.39 U$37.22
N$32: RA.2 RD.1 U10.112
N$33: U9.58 U$37.5
N$34: U9.57 U$37.6
N$35: U9.54 U$37.7
N$36: U9.53 U$37.8
N$37: U9.52 U$37.9
N$38: U9.51 U$37.10
N$39: U9.99 U10.16
N$40: U9.50 U$37.13
N$41: U9.47 U$37.14
N$42: U9.46 U$37.15
N$43: U9.45 U$37.16
N$44: U9.44 U$37.19
N$45: U9.41 U$37.20
N$46: U9.38 U$37.23
N$47: U9.35 U$37.24
N$48: U9.34 U$37.29
N$49: U9.33 U$37.30
N$50: U9.32 U$37.31
N$51: U9.31 U$37.32
N$52: C157.1 R55.2
N$53: U6.5 U$37.35
N$54: U6.3 U$37.36
N$55: U6.1 U$37.37
N$56: R23.2 U6.23 U6.24 U$37.41
N$57: C5.1 C8.1 C9.1 R29.1 U10.9 U10.13
N$58: C5.2 C6.1 C7.1 C8.2 C9.2 R30.2 U10.10 U10.14
N$59: C6.2 U10.11
N$60: C7.2 U10.12
N$61: U10.21 U10.24
N$62: U3.5 U9.10
N$63: U3.6 U9.7
N$64: U3.7 U9.6
N$65: C33.+ U3.2
N$66: C127.2 R4.1 U6.4
N$67: C128.2 R3.1 U6.2
N$68: U4.4 U9.23
N$69: U4.5 U9.20
N$70: U4.6 U9.19
N$71: U4.7 U9.18
N$72: U4.8 U9.15
N$73: U4.10 U9.14
N$74: R11.2 U4.23
N$75: C126.1 R10.2 U4.21
N$76: R34.1 U10.57 U$37.38
N$77: C32.1 R20.2 U3.4
N$78: C31.1 R18.2 U3.1
N$79: C143.1 U4.24
N$80: C125.1 R9.2 U4.19
N$81: C124.1 R8.2 U4.17
N$82: C158.1 R56.2
N$83: C32.2 C34.2 U2.5
N$84: C31.2 U2.10
N$85: C24.2 U2.7
N$86: C28.2 U2.9
N$87: C29_X.2 U2.12
N$88: C30.2 U2.3
N$89: D1.A R19.2 U2.6
N$90: C25.1 R58.2
N$91: C14.1 U5.10
N$93: C26.2 U2.14
N$94: AV.7 C122.1 R57.1 TVS1.3
N$95: C26.1 R57.2
N$96: C_U1.56 U$38.1
N$97: CA6.2 U13.4
N$98: C_U1.55 U$38.2
N$99: U4.13 U5.6
N$100: U4.14 U5.5 U$37.42
N$101: C124.2 U5.3
N$102: C125.2 U5.2
N$103: C126.2 U5.1
N$104: C15.1 R5.2
N$105: C15.2 U5.13
N$106: C16.2 U5.12
N$107: AV.4 C11.1 R7.1 TVS1.5
N$108: AV.3 C12.1 R6.1
N$109: C14.2 R7.2
N$110: C21.1 U5.8
N$112: R13.2 U7.8
N$113: C21.2 R12.2 R13.1
N$114: AV.2 C13.1 R5.1 TVS1.1 TVS1.6
N$115: RGB.6 U4.18
N$116: C_U1.8 JOY.1
N$117: C_U1.54 U$38.3
N$118: C_U1.53 U$38.4
N$119: C_U1.9 JOY.2
N$120: C_U1.51 U$38.5
N$121: C_U1.49 U$38.6
N$122: C_U1.48 U$38.7
N$123: C_U1.47 U$38.8
N$124: U9.40 U$37.21
N$125: C_U1.46 U$38.9
N$126: C_U1.45 U$38.11
N$127: C_U1.44 U$38.10
N$128: C_U1.43 U$38.12
N$129: C_U1.42 U$38.13
N$130: C_U1.41 U$38.14
N$131: BUTT2.2 C_U1.21 TVS6.1
N$132: C_U1.38 U$38.16
N$133: C_U1.37 U$38.18
N$134: C_U1.39 U$38.17
N$135: C_U1.36 U$38.19
N$136: C_U1.35 U$38.20
N$137: C_U1.34 U$38.21
N$138: C_U1.31 U$38.22
N$139: C_U1.30 U$38.23
N$140: C_U1.29 U$38.24
N$141: C_U1.28 U$38.25
N$142: C_U1.27 U$38.26
N$143: C_U1.26 U$38.27
N$144: C_U1.25 U$38.28
N$145: C_U1.24 U$38.29
N$146: C_C14.1 C_R3.1
N$147: 3V3.2 CA12.2
N$148: BUTT2.3 C_U1.17 TVS6.6
N$149: BUTT2.4 C_U1.16 TVS6.5
N$150: BUTT2.5 C_U1.15 TVS6.4
N$151: BUTT2.6 C_U1.14 TVS6.3
N$152: BUTT2.7 C_U1.13 TVS4.1
N$153: BUTT2.8 C_U1.12 TVS4.6
N$157: C_U1.7 JOY.3
N$158: C_U1.6 JOY.6
N$159: BUTT1.4 C_U1.5 TVS5.3
N$160: BUTT1.5 C_U1.4 TVS5.4
N$161: BUTT1.6 C_U1.3 TVS5.5
N$162: BUTT1.7 C_U1.2 TVS5.6
N$163: BUTT1.8 C_U1.58 TVS5.1
N$164: C_R1.1 C_U1.61 JP1.3
N$165: C_C1.2 C_U1.63
N$166: CA9.2 U12.4
N$168: 3V3.3 RG.1
N$170: 3V3.1 CA.1
N$172: LED2.A RE2.1
N$173: LED4.A RE4.1
N$174: LED3.A RE3.1
NMI: U6.7 U10.93 U$37.40
OSCIN1: C39.1 U15.6 X2.1
OSCOUT1: C40_.1 U15.5 X2.2
R58: AV.6 C23.1 R58.1 TVS1.4
RAM0: C132.1 R25.1 R35.2 U9.135 U11.21 U14.21
RAM1: RN2.1 U9.137 U11.19 U14.19
RAM2: R33.1 U9.144 U11.15 U14.15
RAM3: RN2.3 U9.146 U11.13 U14.13
RAM4: RN3.2 U9.153 U11.7 U14.7
RIGHT_AUDIO: C29_X.1 R17.2 U$37.48
SW: 3V3.8 CA.2 DA.- U$52.1
SYSAD0: U9.66 U10.73
SYSAD1: U9.67 U10.70
SYSAD2: U9.68 U10.69
SYSAD3: U9.69 U10.66
SYSAD4: U9.72 U10.64
SYSAD5: U9.73 U10.56
SYSAD6: U9.74 U10.55
SYSAD7: U9.75 U10.51
SYSAD8: U9.78 U10.50
SYSAD9: U9.79 U10.47
SYSAD10: U9.81 U10.45
SYSAD11: U9.84 U10.42
SYSAD12: U9.85 U10.41
SYSAD13: U9.86 U10.38
SYSAD14: U9.87 U10.37
SYSAD15: U9.92 U10.34
SYSAD16: U9.93 U10.33
SYSAD17: U9.94 U10.27
SYSAD18: U9.95 U10.26
SYSAD19: U9.96 U10.22
SYSAD20: U9.102 U10.7
SYSAD21: U9.103 U10.4
SYSAD22: U9.104 U10.3
SYSAD23: U9.107 U10.117
SYSAD24: U9.108 U10.115
SYSAD25: U9.121 U10.98
SYSAD26: U9.122 U10.94
SYSAD27: U9.123 U10.87
SYSAD28: U9.124 U10.86
SYSAD29: U9.59 U10.83
SYSAD30: U9.61 U10.81
SYSAD31: U9.65 U10.77
SYSCMD0: U9.118 U10.100
SYSCMD1: U9.117 U10.103
SYSCMD2: U9.115 U10.106
SYSCMD3: U9.112 U10.109
SYSCMD4: U9.111 U10.111
U2: C25.2 U2.1
U3: U11.22 U14.20
VTERM: CA8.2 R24.2 R25.2 R32.2 RE4.2 RN1.5 RN1.6 RN1.7 RN1.8 RN2.5 RN2.6 RN2.7 RN2.8 RN3.5 RN3.6 RN3.7 RN3.8 U12.5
